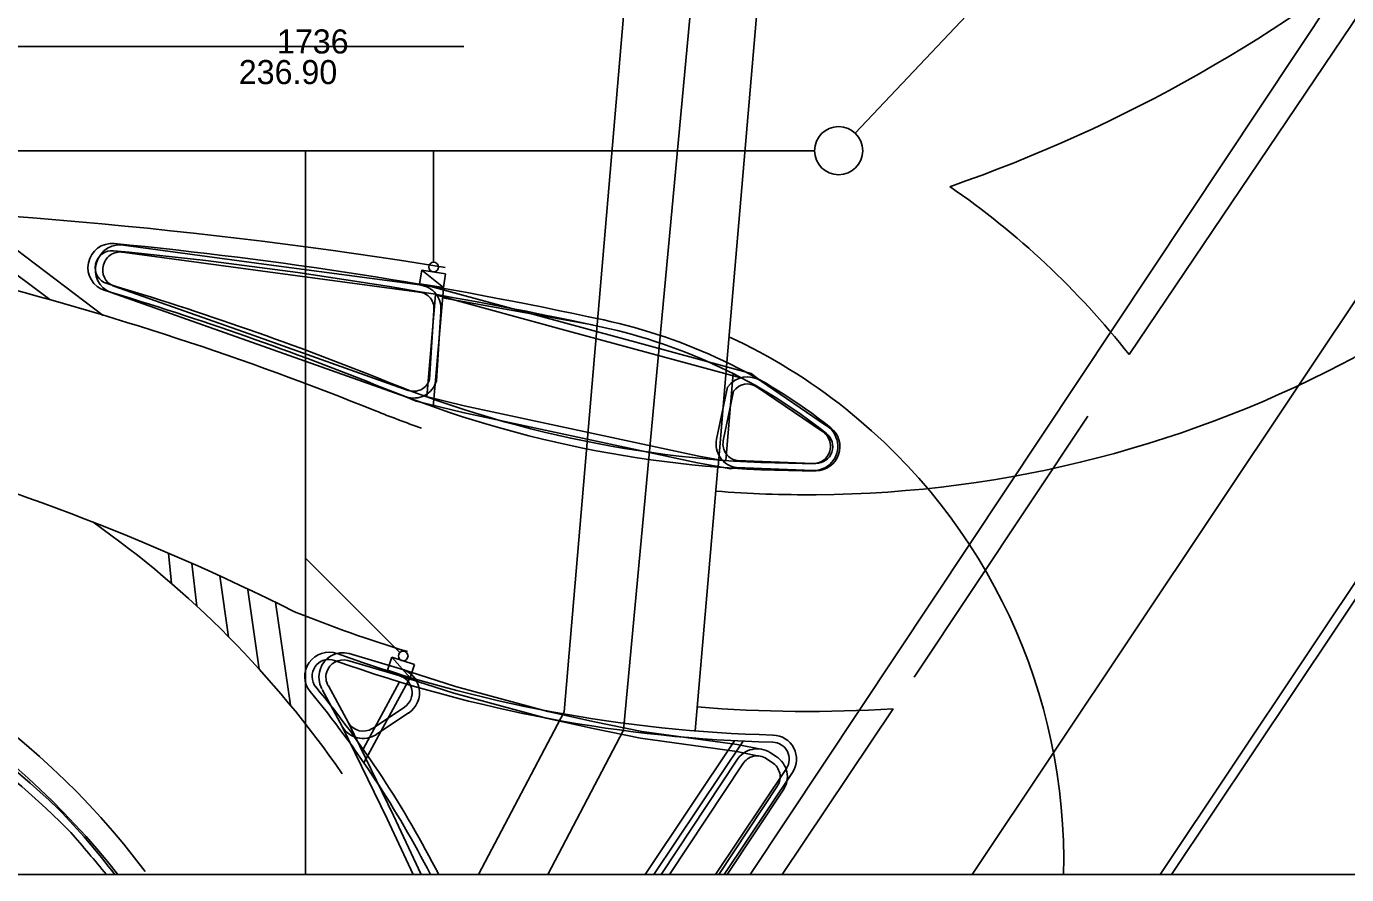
# Model space of a CAD drawing. Extents: x -264165 to -263733, y -1242319 to -1242245.
# Drawn here: x -263825.46 to -263798.04, y -1242319.19 to -1242301.57 of the extents above; entities that cross this region are included whole.
import ezdxf

# ---------------------------------------------------------------- set-up
doc = ezdxf.new("R2010")
doc.units = 0
for name, color, linetype in [('KFA_BOD_CISLO', 7, 'Continuous'), ('KFA_BOD_VYSKA', 7, 'Continuous'), ('PROJEKT_OBRUBNIKY_KOMUNIKACIE', 7, 'Continuous'), ('PROJEKT_TDZ_VODOROVNE', 7, 'Continuous'), ('RAM_NA_TLAC_1-250', 7, 'Continuous'), ('SITUACIA_DSP_2D', 7, 'Continuous'), ('SO_20-1_OBRUBNIKY_DOLNA_HRANA', 7, 'Continuous'), ('SO_20-1_OBRUBNIKY_HORNA_HRANA', 7, 'Continuous')]:
    doc.layers.add(name, color=color, linetype=linetype)

msp = doc.modelspace()

# ---------------------------------------------------------------- linework, layer by layer
at = {"layer": 'PROJEKT_OBRUBNIKY_KOMUNIKACIE'}
for p, q in [((-263816.802, -1242307.008), (-263817.012, -1242309.469)), ((-263816.964, -1242307.132), (-263817.145, -1242309.262)), ((-263816.819, -1242307.205), (-263813.706, -1242307.767)), ((-263810.912, -1242308.547), (-263811.097, -1242310.721)), ((-263810.781, -1242308.779), (-263810.935, -1242310.583)), ((-263818.469, -1242316.58), (-263817.711, -1242315.183)), ((-263818.453, -1242316.866), (-263817.491, -1242315.093)), ((-263810.751, -1242316.405), (-263812.608, -1242319.185)), ((-263810.576, -1242316.414), (-263812.427, -1242319.185)), ((-263809.676, -1242316.98), (-263811.149, -1242319.185)), ((-263809.551, -1242317.064), (-263810.969, -1242319.185))]:
    msp.add_line(p, q, dxfattribs=at)
for centre, radius, start, end in [((-263823.686, -1242306.574), 0.5, 84.5031, 253.3726), ((-263832, -1242392.966), 87.291, 77.74517, 84.50312), ((-263823.686, -1242306.574), 0.35, 84.5031, 253.3726), ((-263832, -1242392.966), 87.141, 77.74517, 84.50312), ((-263842.678, -1242370.168), 66.019, 68.01969, 73.37264), ((-263842.678, -1242370.168), 65.869, 68.01969, 73.37264), ((-263815.913, -1242318.902), 11.35, 51.4912, 77.7452), ((-263815.913, -1242318.902), 11.5, 51.4912, 77.7452), ((-263809.228, -1242287.295), 23.5, 248.0197, 270.4085), ((-263809.228, -1242287.295), 23.35, 248.0197, 270.4085), ((-263809.064, -1242310.295), 0.35, 270.4085, 51.4912), ((-263809.064, -1242310.295), 0.5, 270.4085, 51.4912), ((-263836.184, -1242329.025), 16, 37.9535, 76.9695), ((-263819.181, -1242315.066), 0.5, 70.2828, 219.3857), ((-263809.228, -1242287.295), 29, 250.2828, 268.5641), ((-263819.181, -1242315.066), 0.35, 70.2828, 219.3857), ((-263809.228, -1242287.295), 29.15, 250.2828, 268.5641), ((-263836.184, -1242329.025), 21.5, 27.2382, 39.3857), ((-263836.184, -1242329.025), 21.65, 27.0341, 39.3857), ((-263809.967, -1242316.786), 0.5, 326.2529, 88.5641), ((-263809.967, -1242316.786), 0.35, 326.2529, 88.5641)]:
    msp.add_arc(centre, radius, start, end, dxfattribs=at)
at = {"layer": 'PROJEKT_TDZ_VODOROVNE'}
for p, q in [((-263805.817, -1242319.185), (-263789.385, -1242294.564)), ((-263786.678, -1242296.363), (-263801.914, -1242319.185)), ((-263786.512, -1242296.474), (-263801.673, -1242319.185)), ((-263796.435, -1242299.302), (-263802.558, -1242308.383)), ((-263810.915, -1242308.545), (-263810.255, -1242300.841)), ((-263913.857, -1242301.982), (-263816.374, -1242301.982)), ((-263827.448, -1242305.4), (-263824.977, -1242307.241)), ((-263826.672, -1242305.448), (-263823.87, -1242307.573)), ((-263807.021, -1242315.081), (-263803.412, -1242309.66)), ((-263811.571, -1242316.2), (-263811.101, -1242310.72)), ((-263822.515, -1242312.506), (-263822.452, -1242313.137)), ((-263822.025, -1242312.72), (-263821.925, -1242313.608)), ((-263821.448, -1242312.98), (-263821.265, -1242314.247)), ((-263820.866, -1242313.273), (-263820.628, -1242314.918)), ((-263820.29, -1242313.528), (-263819.981, -1242315.667)), ((-263809.763, -1242319.185), (-263807.46, -1242315.74))]:
    msp.add_line(p, q, dxfattribs=at)
for points in [[(-263816.072, -1242319.185), (-263814.291, -1242315.804), (-263813.06, -1242301.353), (-263812.968, -1242299.181), (-263802.618, -1242291.831), (-263801.478, -1242290.893), (-263800.257, -1242289.755), (-263799.049, -1242288.464), (-263798.027, -1242287.218), (-263780.363, -1242261.313)], [(-263814.635, -1242319.185), (-263813.062, -1242316.188), (-263811.682, -1242301.389), (-263811.608, -1242300.055), (-263801.705, -1242293.023), (-263800.489, -1242292.021), (-263799.197, -1242290.817), (-263797.92, -1242289.454), (-263796.825, -1242288.118), (-263780.363, -1242263.975)]]:
    msp.add_lwpolyline(points, dxfattribs=at)
for centre, radius, start, end in [((-263816.477, -1242275.476), 31.135, 289.1139, 310.0684), ((-263809.228, -1242287.295), 24, 270.4085, 326.3969), ((-263815.913, -1242318.902), 17, 38.2267, 55.4906), ((-263842.678, -1242370.168), 65.369, 68.01969, 83.40081), ((-263833.602, -1242410.935), 105.714, 80.83552, 89.15278), ((-263815.913, -1242318.902), 12, 51.4912, 65.1468), ((-263842.518, -1242358.966), 50.583, 63.4329, 86.4022), ((-263809.228, -1242287.295), 24, 248.0197, 250.4574), ((-263815.913, -1242318.902), 12, 358.6494, 51.4912), ((-263809.228, -1242287.295), 24, 265.4211, 270.4085), ((-263836.184, -1242329.025), 21, 34.6339, 54.8237), ((-263836.225, -1242329.073), 16.555, 36.9462, 76.8694), ((-263809.228, -1242287.295), 28.5, 248.0197, 253.0257), ((-263809.228, -1242287.295), 28.5, 265.3711, 273.5562)]:
    msp.add_arc(centre, radius, start, end, dxfattribs=at)
at = {"layer": 'RAM_NA_TLAC_1-250'}
msp.add_lwpolyline([(-264165.363, -1242244.935), (-263732.863, -1242244.935), (-263732.863, -1242319.185), (-264165.363, -1242319.185)], close=True, dxfattribs=at)
at = {"layer": 'SITUACIA_DSP_2D'}
for p, q in [((-263810.431, -1242319.185), (-263780.363, -1242273.949)), ((-263780.363, -1242274.247), (-263808.248, -1242303.783)), ((-263809.091, -1242304.153), (-263853.415, -1242304.148)), ((-263819.667, -1242319.185), (-263819.667, -1242304.147)), ((-263817.005, -1242306.465), (-263817.005, -1242304.152)), ((-263817.296, -1242306.914), (-263817.252, -1242306.627)), ((-263817.252, -1242306.627), (-263817.296, -1242306.914)), ((-263817.252, -1242306.627), (-263816.757, -1242306.703)), ((-263816.802, -1242306.99), (-263817.252, -1242306.627)), ((-263816.802, -1242306.99), (-263817.252, -1242306.627)), ((-263816.757, -1242306.703), (-263816.802, -1242306.99)), ((-263816.802, -1242306.99), (-263817.296, -1242306.914)), ((-263817.296, -1242306.914), (-263816.802, -1242306.99)), ((-263816.803, -1242307.008), (-263817.012, -1242309.468)), ((-263816.964, -1242307.132), (-263817.145, -1242309.262)), ((-263810.912, -1242308.547), (-263811.097, -1242310.721)), ((-263810.781, -1242308.779), (-263810.935, -1242310.583)), ((-263817.708, -1242314.574), (-263819.667, -1242312.615)), ((-263817.966, -1242314.94), (-263817.874, -1242314.665)), ((-263817.874, -1242314.665), (-263817.966, -1242314.94)), ((-263817.874, -1242314.665), (-263817.4, -1242314.824)), ((-263817.492, -1242315.099), (-263817.874, -1242314.665)), ((-263817.492, -1242315.099), (-263817.874, -1242314.665)), ((-263817.492, -1242315.099), (-263817.966, -1242314.94)), ((-263817.966, -1242314.94), (-263817.492, -1242315.099)), ((-263817.4, -1242314.824), (-263817.492, -1242315.099)), ((-263818.469, -1242316.58), (-263817.711, -1242315.183)), ((-263818.453, -1242316.866), (-263817.491, -1242315.093)), ((-263810.751, -1242316.405), (-263812.608, -1242319.185)), ((-263810.576, -1242316.414), (-263812.427, -1242319.185)), ((-263809.676, -1242316.98), (-263811.149, -1242319.185)), ((-263809.551, -1242317.064), (-263810.969, -1242319.185))]:
    msp.add_line(p, q, dxfattribs=at)
for centre, radius in [((-263808.591, -1242304.147), 0.5), ((-263817.005, -1242306.565), 0.1), ((-263817.637, -1242314.644), 0.1)]:
    msp.add_circle(centre, radius, dxfattribs=at)
for centre, radius, start, end in [((-263823.686, -1242306.574), 0.5, 84.5031, 253.3726), ((-263832, -1242392.966), 87.291, 77.74517, 84.50312), ((-263823.686, -1242306.574), 0.35, 84.5031, 253.3726), ((-263832, -1242392.966), 87.141, 77.74517, 84.50312), ((-263842.678, -1242370.168), 66.019, 68.01969, 73.37264), ((-263842.678, -1242370.168), 65.869, 68.01969, 73.37264), ((-263815.913, -1242318.902), 11.35, 51.4912, 77.7452), ((-263815.913, -1242318.902), 11.5, 51.4912, 77.7452), ((-263809.228, -1242287.295), 23.5, 248.0197, 270.4085), ((-263809.228, -1242287.295), 23.35, 248.0197, 270.4085), ((-263809.064, -1242310.295), 0.35, 270.4085, 51.4912), ((-263809.064, -1242310.295), 0.5, 270.4085, 51.4912), ((-263836.184, -1242329.025), 16, 37.9534, 76.9695), ((-263819.181, -1242315.066), 0.5, 70.2828, 219.3857), ((-263809.228, -1242287.295), 29, 250.2828, 268.5641), ((-263819.181, -1242315.066), 0.35, 70.2828, 219.3857), ((-263809.228, -1242287.295), 29.15, 250.2828, 268.5641), ((-263836.184, -1242329.025), 21.5, 27.2381, 39.3857), ((-263836.184, -1242329.025), 21.65, 27.034, 39.3857), ((-263809.967, -1242316.786), 0.5, 326.2529, 88.5641), ((-263809.967, -1242316.786), 0.35, 326.2529, 88.5641)]:
    msp.add_arc(centre, radius, start, end, dxfattribs=at)
at = {"layer": 'SO_20-1_OBRUBNIKY_DOLNA_HRANA'}
for p, q in [((-263817.063, -1242306.967), (-263817.288, -1242306.937)), ((-263810.406, -1242308.774), (-263817.063, -1242306.967)), ((-263820.884, -1242308.09), (-263817.579, -1242309.261)), ((-263810.406, -1242308.774), (-263810.197, -1242308.936)), ((-263817.365, -1242309.349), (-263817.579, -1242309.261)), ((-263810.829, -1242310.758), (-263810.713, -1242310.731))]:
    msp.add_line(p, q, dxfattribs=at)
for points in [[(-263817.288, -1242306.937), (-263820.425, -1242306.521), (-263823.4, -1242306.12)], [(-263823.703, -1242307.096), (-263820.884, -1242308.09)], [(-263816.946, -1242308.93), (-263816.856, -1242307.496)], [(-263808.866, -1242309.846), (-263810.197, -1242308.936)], [(-263810.897, -1242309.063), (-263811.127, -1242310.142)], [(-263817.365, -1242309.349), (-263816.395, -1242309.589), (-263811.523, -1242310.634), (-263810.829, -1242310.758)], [(-263810.713, -1242310.731), (-263809.129, -1242310.789)], [(-263817.69, -1242314.913), (-263818.761, -1242314.594)], [(-263810.206, -1242316.578), (-263810.698, -1242316.485), (-263812.677, -1242316.21), (-263813.66, -1242316.015), (-263814.633, -1242315.798), (-263816.547, -1242315.28), (-263817.69, -1242314.913)], [(-263819.319, -1242315.341), (-263818.902, -1242316.108)], [(-263818.201, -1242316.278), (-263817.525, -1242315.828)], [(-263818.902, -1242316.108), (-263817.973, -1242318.024), (-263817.431, -1242319.185)], [(-263810.704, -1242316.807), (-263812.279, -1242319.185)], [(-263809.892, -1242316.735), (-263810.008, -1242316.657)], [(-263810.906, -1242319.185), (-263809.743, -1242317.428)]]:
    msp.add_lwpolyline(points, dxfattribs=at)
for centre, major_axis, ratio, start_param, end_param in [((-263823.524, -1242306.605), (0.185, 0.465), 0.999783, 0.129335, 1.693518), ((-263823.537, -1242306.629), (-0.201, -0.453), 0.999743, 4.819194, 6.358079), ((-263817.347, -1242307.429), (-0.223, 0.443), 0.999317, 4.112578, 5.697553), ((-263817.423, -1242308.788), (0.483, 0.121), 0.999839, 4.148248, 5.748493), ((-263810.483, -1242309.349), (-0.502, 0.041), 0.998209, 4.188918, 5.758624), ((-263809.118, -1242310.288), (0.193, 0.471), 0.999988, 4.374498, 6.15423), ((-263810.643, -1242310.242), (0.359, -0.34), 0.999903, 3.695611, 5.327884), ((-263809.106, -1242310.293), (-0.189, -0.46), 0.999728, 0.34373, 1.224576), ((-263836.917, -1242330.389), (-12.568, 12.147), 0.998664, 4.713467, 5.197044), ((-263818.893, -1242315.066), (0.148, -0.467), 0.999867, 2.562738, 4.12235), ((-263818.868, -1242315.085), (0.045, -0.517), 0.999806, 4.320521, 5.104257), ((-263817.803, -1242315.406), (0.39, 0.323), 0.999315, 4.602925, 6.93754), ((-263818.47, -1242315.857), (-0.486, 0.118), 0.999915, 0.764319, 2.377274), ((-263810.284, -1242317.065), (-0.259, 0.419), 0.999812, 5.134851, 6.750861), ((-263810.141, -1242317.151), (0.065, 0.481), 0.999991, 4.238012, 5.877529), ((-263835.299, -1242328.082), (-9.097, 11.695), 0.990566, 4.702683, 4.823964)]:
    msp.add_ellipse(centre, major_axis=major_axis, ratio=ratio, start_param=start_param, end_param=end_param, dxfattribs=at)
at = {"layer": 'SO_20-1_OBRUBNIKY_HORNA_HRANA'}
msp.add_line((-263817.531, -1242309.127), (-263820.836, -1242307.954), dxfattribs=at)
for points in [[(-263817.303, -1242307.084), (-263820.446, -1242306.665), (-263823.42, -1242306.265)], [(-263823.65, -1242306.961), (-263820.836, -1242307.954)], [(-263810.62, -1242308.866), (-263814.206, -1242307.895), (-263816.937, -1242307.151)], [(-263817.088, -1242308.892), (-263817, -1242307.47)], [(-263810.775, -1242309.146), (-263810.987, -1242310.177)], [(-263808.95, -1242309.964), (-263810.282, -1242309.057)], [(-263817.212, -1242309.239), (-263816.368, -1242309.447), (-263811.493, -1242310.492), (-263811.003, -1242310.58)], [(-263810.691, -1242310.583), (-263809.125, -1242310.643)], [(-263817.727, -1242315.051), (-263818.789, -1242314.736)], [(-263810.25, -1242316.722), (-263810.709, -1242316.628), (-263812.704, -1242316.349), (-263813.689, -1242316.152), (-263814.669, -1242315.935), (-263816.585, -1242315.418), (-263817.727, -1242315.051)], [(-263819.192, -1242315.267), (-263818.773, -1242316.035)], [(-263818.28, -1242316.154), (-263817.608, -1242315.704)], [(-263818.773, -1242316.035), (-263817.84, -1242317.955), (-263817.267, -1242319.185)], [(-263810.584, -1242316.886), (-263812.107, -1242319.185)], [(-263809.97, -1242316.859), (-263810.089, -1242316.78)], [(-263811.081, -1242319.185), (-263809.861, -1242317.343)]]:
    msp.add_lwpolyline(points, dxfattribs=at)
for centre, major_axis, ratio, start_param, end_param in [((-263823.519, -1242306.604), (0.235, 0.264), 0.999068, 0.442251, 2.051271), ((-263823.525, -1242306.629), (-0.123, -0.333), 0.999597, 4.748011, 6.276343), ((-263817.341, -1242307.426), (-0.027, 0.343), 0.999831, 4.506293, 6.094133), ((-263817.42, -1242308.802), (-0.293, -0.18), 0.999477, 0.692286, 2.325931), ((-263810.484, -1242309.349), (-0.307, 0.179), 0.999697, 4.635173, 6.202132), ((-263809.124, -1242310.284), (-0.341, 0.127), 0.999992, 2.744279, 4.570945), ((-263810.652, -1242310.243), (0.136, -0.314), 0.999837, 4.109578, 5.759605), ((-263809.115, -1242310.288), (-0.172, -0.311), 0.99925, 0.476223, 1.31312), ((-263837.329, -1242331.009), (-13.346, 12.171), 0.997839, 4.663107, 5.155176), ((-263818.881, -1242315.086), (0.067, -0.355), 0.999729, 2.699114, 4.216297), ((-263818.883, -1242315.084), (-0.063, -0.354), 0.999357, 4.579753, 5.422246), ((-263817.816, -1242315.405), (0.31, 0.192), 0.999422, 4.763927, 7.052938), ((-263818.467, -1242315.846), (0.335, -0.13), 0.999891, 4.064262, 5.628365), ((-263810.285, -1242317.071), (-0.288, 0.202), 0.999767, 4.729783, 6.338871), ((-263810.156, -1242317.155), (-0.077, 0.341), 0.999809, 3.924248, 5.50053), ((-263849.035, -1242339.606), (-22.317, 24.858), 0.971582, 4.662656, 4.696983)]:
    msp.add_ellipse(centre, major_axis=major_axis, ratio=ratio, start_param=start_param, end_param=end_param, dxfattribs=at)

# ---------------------------------------------------------------- texts
at = {"layer": 'KFA_BOD_CISLO'}
msp.add_text('1736', height=0.5, dxfattribs=at).set_placement((-263820.258, -1242302.128))
at = {"layer": 'KFA_BOD_VYSKA'}
msp.add_text('236.90', height=0.5, dxfattribs=at).set_placement((-263821.052, -1242302.764))

doc.saveas('drawing.dxf')
